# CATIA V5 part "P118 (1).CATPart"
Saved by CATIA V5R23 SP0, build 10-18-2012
Part number: 05-LICP-T02-E-S13-P118 (1)
Definition: butee a aiguilles
Description: butee_a_aiguilles_ax_19_32_01
Bounding box of the stored display mesh (mm): x 0.998 to 2.2, y -15.202 to 15.202, z -15.202 to 15.202
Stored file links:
  C:\wamp\www\COURS\CONCEPTION GMP1\TITRE 02-SEMESTRE 2\03-TP7-PRESSE MECANIQUE\eleve\P118 (1).CATPart
  P:\etudiants\lpro\ProjetsTUT-LP-2005\Deletré Makowski Theallier\05-LICP-T02 - Assemblage Presse Mécanique\- Presse Mecanique (Motion CATIA 2004+).CATProduct
  C:\wamp\www\COURS\CONCEPTION GMP1\TITRE 02-SEMESTRE 2\03-TP7-PRESSE MECANIQUE\eleve\P118 (4).CATPart
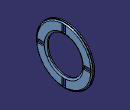
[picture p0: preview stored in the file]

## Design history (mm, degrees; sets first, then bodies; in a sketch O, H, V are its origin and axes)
Set1
  DatumSurface1: linked copy from another document
Set2
  Plane1: type Offset, RefPlane DatumSurface1, Offset 2.8
Body1 (main body)
  Solid1: solid without history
